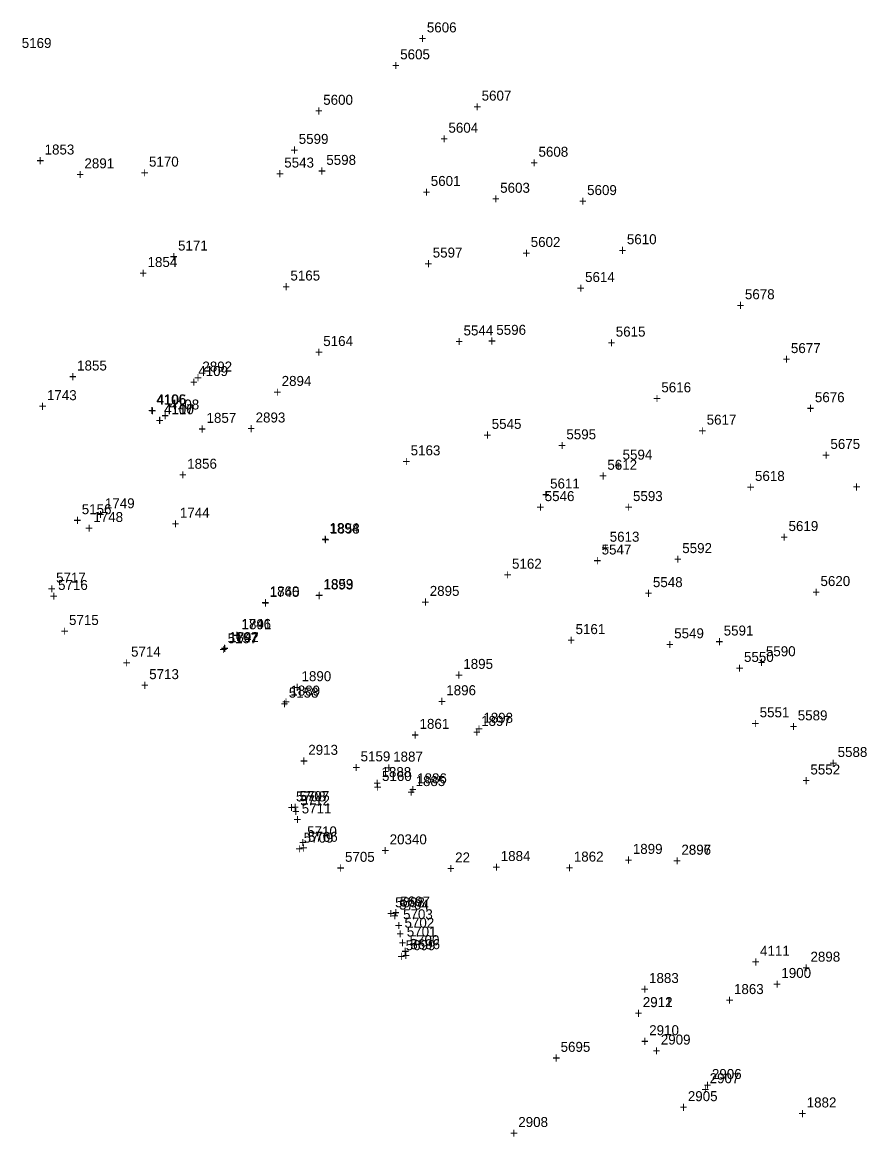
# Model space of a CAD drawing. Extents: x 1036751 to 1042192, y 772604 to 785439.
# Drawn here: x 1040253.8 to 1040463.6, y 775179.4 to 775458.3 of the extents above; entities that cross this region are included whole.
import ezdxf

# ---------------------------------------------------------------- set-up
doc = ezdxf.new("R2010")
doc.units = 0
for name, color, linetype in [('S_Control_Geodetic_ControlPoint', 7, 'Continuous'), ('S_Curb_Type_3', 7, 'Continuous'), ('S_Drainage_Culvert_Top', 7, 'Continuous'), ('S_Drainage_Invert', 7, 'Continuous'), ('S_Drainage_Waterway', 7, 'Continuous'), ('S_Fencing_ChainLink', 7, 'Continuous'), ('S_Ground_Elevation', 7, 'Continuous'), ('S_Misc_MiscItems', 7, 'Continuous'), ('S_Property_ConcPad', 7, 'Continuous'), ('S_Roadway_Centerline', 7, 'Continuous'), ('S_Roadway_Edge_Pavement', 7, 'Continuous'), ('S_Roadway_Edge_TW', 7, 'Continuous'), ('S_Traffic_Sign_SinglePost', 7, 'Continuous'), ('S_Utilities_GuyWire3', 7, 'Continuous'), ('S_Utilities_Hydrant', 7, 'Continuous'), ('S_Utilities_Pole_Power', 7, 'Continuous'), ('S_Utilities_Pole_Support3', 7, 'Continuous'), ('S_Utilities_UG_Water_Gate', 7, 'Continuous'), ('S_Utilities_UG_Water_Line', 7, 'Continuous'), ('S_Utilities_UG_Water_Shutoff', 7, 'Continuous')]:
    doc.layers.add(name, color=color, linetype=linetype)

msp = doc.modelspace()

# ---------------------------------------------------------------- texts
at = {"layer": 'S_Control_Geodetic_ControlPoint'}
for s, p in [('22', (1040362.11, 775248.06)), ('22', (1040362.11, 775248.06)), ('22', (1040362.11, 775248.06)), ('22', (1040362.11, 775248.06)), ('22', (1040362.11, 775248.06)), ('22', (1040362.11, 775248.06)), ('22', (1040362.11, 775248.06)), ('22', (1040362.11, 775248.06)), ('22', (1040362.11, 775248.06)), ('22', (1040362.11, 775248.06)), ('+', (1040360.05, 775245.31)), ('+', (1040360.05, 775245.31)), ('+', (1040360.05, 775245.31)), ('+', (1040360.05, 775245.31)), ('+', (1040360.05, 775245.31)), ('+', (1040360.05, 775245.31)), ('+', (1040360.05, 775245.31)), ('+', (1040360.05, 775245.31)), ('+', (1040360.05, 775245.31)), ('+', (1040360.05, 775245.31))]:
    msp.add_text(s, height=2.5, dxfattribs=at).set_placement(p)
at = {"layer": 'S_Curb_Type_3'}
for s, p in [('5156', (1040268.68, 775335.22)), ('+', (1040266.61, 775332.47)), ('5157', (1040305.19, 775302.92)), ('+', (1040303.13, 775300.17)), ('5158', (1040320.49, 775289.3)), ('+', (1040318.43, 775286.55)), ('5159', (1040338.45, 775273.35)), ('+', (1040336.39, 775270.6)), ('5160', (1040343.81, 775268.44)), ('+', (1040341.75, 775265.69))]:
    msp.add_text(s, height=2.5, dxfattribs=at).set_placement(p)
at = {"layer": 'S_Drainage_Culvert_Top'}
for s, p in [('2897', (1040418.73, 775250.01)), ('+', (1040416.67, 775247.26)), ('2911', (1040409.07, 775211.84)), ('+', (1040407.01, 775209.09))]:
    msp.add_text(s, height=2.5, dxfattribs=at).set_placement(p)
at = {"layer": 'S_Drainage_Invert'}
for s, p in [('2896', (1040418.71, 775249.98)), ('+', (1040416.65, 775247.23)), ('2912', (1040409.07, 775211.86)), ('+', (1040407.01, 775209.11))]:
    msp.add_text(s, height=2.5, dxfattribs=at).set_placement(p)
at = {"layer": 'S_Drainage_Waterway'}
for s, p in [('5543', (1040319.35, 775421.98)), ('+', (1040317.29, 775419.23)), ('5544', (1040364.21, 775379.96)), ('+', (1040362.15, 775377.21)), ('5545', (1040371.26, 775356.57)), ('+', (1040369.2, 775353.82)), ('5546', (1040384.53, 775338.49)), ('+', (1040382.47, 775335.74)), ('5547', (1040398.77, 775325.13)), ('+', (1040396.71, 775322.38)), ('5548', (1040411.6, 775316.96)), ('+', (1040409.54, 775314.21)), ('5549', (1040416.92, 775304.16)), ('+', (1040414.86, 775301.41)), ('5550', (1040434.39, 775298.24)), ('+', (1040432.32, 775295.49)), ('5551', (1040438.31, 775284.39)), ('+', (1040436.25, 775281.64)), ('5552', (1040451.01, 775270.07)), ('+', (1040448.95, 775267.32))]:
    msp.add_text(s, height=2.5, dxfattribs=at).set_placement(p)
at = {"layer": 'S_Fencing_ChainLink'}
for s, p in [('2907', (1040425.8, 775192.8)), ('+', (1040423.74, 775190.05)), ('2908', (1040377.91, 775181.84)), ('+', (1040375.85, 775179.09))]:
    msp.add_text(s, height=2.5, dxfattribs=at).set_placement(p)
at = {"layer": 'S_Ground_Elevation'}
for s, p in [('5606', (1040355.03, 775455.8)), ('5169', (1040253.66, 775451.9)), ('+', (1040352.97, 775453.05)), ('5605', (1040348.36, 775449.06)), ('+', (1040346.3, 775446.31)), ('5600', (1040329.1, 775437.68)), ('5607', (1040368.74, 775438.73)), ('+', (1040327.04, 775434.93)), ('+', (1040366.68, 775435.98)), ('5604', (1040360.43, 775430.69)), ('5599', (1040322.97, 775427.9)), ('+', (1040358.37, 775427.94)), ('+', (1040320.91, 775425.15)), ('5608', (1040382.97, 775424.68)), ('5170', (1040285.5, 775422.21)), ('5598', (1040329.87, 775422.65)), ('+', (1040380.91, 775421.93)), ('+', (1040283.44, 775419.46)), ('+', (1040327.81, 775419.9)), ('5601', (1040356.01, 775417.37)), ('5603', (1040373.38, 775415.66)), ('5609', (1040395.13, 775415.09)), ('+', (1040353.95, 775414.62)), ('+', (1040371.32, 775412.91)), ('+', (1040393.07, 775412.34)), ('5171', (1040292.77, 775401.21)), ('5602', (1040381.02, 775402.09)), ('5610', (1040405.08, 775402.79)), ('+', (1040290.71, 775398.46)), ('5597', (1040356.5, 775399.45)), ('+', (1040378.96, 775399.34)), ('+', (1040403.02, 775400.04)), ('+', (1040354.44, 775396.7)), ('5165', (1040320.89, 775393.7)), ('5614', (1040394.62, 775393.32)), ('+', (1040318.83, 775390.95)), ('+', (1040392.56, 775390.57)), ('5678', (1040434.62, 775389.02)), ('+', (1040432.56, 775386.27)), ('5596', (1040372.41, 775380.11)), ('5615', (1040402.3, 775379.67)), ('5164', (1040329.11, 775377.3)), ('+', (1040370.35, 775377.36)), ('+', (1040400.24, 775376.92)), ('5677', (1040446.13, 775375.54)), ('+', (1040327.05, 775374.55)), ('+', (1040444.07, 775372.79)), ('5616', (1040413.71, 775365.72)), ('+', (1040411.65, 775362.97)), ('5676', (1040452.13, 775363.25)), ('+', (1040450.07, 775360.5)), ('5617', (1040425.05, 775357.62)), ('5595', (1040389.94, 775353.96)), ('+', (1040422.99, 775354.87)), ('+', (1040387.88, 775351.21)), ('5675', (1040456.01, 775351.54)), ('5163', (1040350.98, 775349.94)), ('5594', (1040404.01, 775348.87)), ('+', (1040453.95, 775348.79)), ('+', (1040348.92, 775347.19)), ('5612', (1040400.2, 775346.33)), ('+', (1040401.94, 775346.12)), ('+', (1040398.14, 775343.58)), ('5618', (1040437.14, 775343.54)), ('5611', (1040385.87, 775341.65)), ('+', (1040435.08, 775340.79)), ('+', (1040461.6, 775340.82)), ('+', (1040383.81, 775338.9)), ('5593', (1040406.61, 775338.5)), ('+', (1040404.55, 775335.75)), ('5619', (1040445.54, 775331)), ('5613', (1040400.79, 775328.32)), ('5592', (1040418.94, 775325.48)), ('+', (1040443.48, 775328.25)), ('+', (1040398.72, 775325.57)), ('5162', (1040376.34, 775321.57)), ('+', (1040416.88, 775322.73)), ('+', (1040374.28, 775318.82)), ('5620', (1040453.53, 775317.23)), ('+', (1040451.47, 775314.48)), ('5161', (1040392.24, 775305.21)), ('5591', (1040429.31, 775304.85)), ('+', (1040390.18, 775302.46)), ('+', (1040427.25, 775302.1)), ('5590', (1040439.87, 775299.67)), ('+', (1040437.81, 775296.92)), ('5589', (1040447.84, 775283.62)), ('+', (1040445.78, 775280.87)), ('5588', (1040457.82, 775274.45)), ('+', (1040455.76, 775271.7))]:
    msp.add_text(s, height=2.5, dxfattribs=at).set_placement(p)
at = {"layer": 'S_Misc_MiscItems'}
for s, p in [('5717', (1040262.25, 775318.1)), ('+', (1040260.19, 775315.35)), ('5716', (1040262.75, 775316.25)), ('+', (1040260.69, 775313.5)), ('5715', (1040265.49, 775307.48)), ('+', (1040263.43, 775304.73)), ('5714', (1040281.01, 775299.57)), ('+', (1040278.94, 775296.82)), ('5713', (1040285.55, 775293.93)), ('+', (1040283.49, 775291.18)), ('5712', (1040323.35, 775262.33)), ('+', (1040321.29, 775259.58)), ('5711', (1040323.72, 775260.32)), ('+', (1040321.66, 775257.57)), ('5710', (1040325.07, 775254.58)), ('+', (1040323.01, 775251.83)), ('5705', (1040334.55, 775248.21)), ('+', (1040332.49, 775245.46)), ('5704', (1040348.1, 775236.26)), ('5703', (1040349.08, 775233.83)), ('+', (1040346.04, 775233.51)), ('+', (1040347.02, 775231.08)), ('5702', (1040349.44, 775231.72)), ('+', (1040347.38, 775228.97)), ('5701', (1040350.01, 775229.49)), ('+', (1040347.94, 775226.74)), ('5700', (1040350.73, 775227.35)), ('+', (1040348.66, 775224.6)), ('5695', (1040388.5, 775200.65)), ('+', (1040386.44, 775197.9))]:
    msp.add_text(s, height=2.5, dxfattribs=at).set_placement(p)
at = {"layer": 'S_Property_ConcPad'}
for s, p in [('5708', (1040322.28, 775263.33)), ('5707', (1040323.16, 775263.4)), ('+', (1040320.22, 775260.58)), ('+', (1040321.1, 775260.65)), ('5709', (1040324.21, 775253.01)), ('5706', (1040325.29, 775253.22)), ('+', (1040323.23, 775250.47)), ('+', (1040322.15, 775250.26)), ('5698', (1040347.09, 775236.82)), ('5697', (1040348.37, 775237.03)), ('+', (1040345.03, 775234.07)), ('+', (1040346.31, 775234.28)), ('5699', (1040349.73, 775226.09)), ('5696', (1040350.89, 775226.34)), ('+', (1040347.67, 775223.34)), ('+', (1040348.83, 775223.59))]:
    msp.add_text(s, height=2.5, dxfattribs=at).set_placement(p)
at = {"layer": 'S_Roadway_Centerline'}
for s, p in [('1743', (1040259.97, 775363.76)), ('+', (1040257.91, 775361.01)), ('1744', (1040293.23, 775334.34)), ('+', (1040291.17, 775331.59)), ('1860', (1040315.7, 775314.65)), ('1745', (1040315.73, 775314.53)), ('+', (1040313.64, 775311.9)), ('+', (1040313.66, 775311.78)), ('1861', (1040353.2, 775281.49)), ('+', (1040351.14, 775278.74)), ('1862', (1040391.81, 775248.27)), ('+', (1040389.75, 775245.52)), ('1863', (1040431.88, 775215.11)), ('+', (1040429.82, 775212.36))]:
    msp.add_text(s, height=2.5, dxfattribs=at).set_placement(p)
at = {"layer": 'S_Roadway_Edge_Pavement'}
for s, p in [('1853', (1040259.38, 775425.24)), ('+', (1040257.32, 775422.49)), ('1854', (1040285.14, 775397.08)), ('+', (1040283.08, 775394.33)), ('1857', (1040299.9, 775358.08)), ('+', (1040297.84, 775355.33)), ('1748', (1040271.58, 775333.26)), ('+', (1040269.52, 775330.51)), ('1894', (1040330.66, 775330.5)), ('1858', (1040330.8, 775330.37)), ('+', (1040328.6, 775327.75)), ('+', (1040328.74, 775327.62)), ('1892', (1040305.51, 775303.21)), ('1747', (1040305.54, 775303.15)), ('+', (1040303.45, 775300.46)), ('+', (1040303.48, 775300.4)), ('1895', (1040364.15, 775296.5)), ('+', (1040362.09, 775293.75)), ('1889', (1040320.88, 775289.82)), ('+', (1040318.81, 775287.07)), ('1898', (1040369.16, 775283.01)), ('+', (1040367.1, 775280.26)), ('1888', (1040343.68, 775269.42)), ('1885', (1040352.21, 775267.17)), ('+', (1040341.62, 775266.67)), ('+', (1040350.14, 775264.42)), ('1899', (1040406.57, 775250.2)), ('1884', (1040373.52, 775248.41)), ('+', (1040371.46, 775245.66)), ('+', (1040404.5, 775247.45)), ('1883', (1040410.63, 775217.88)), ('1900', (1040443.74, 775219.15)), ('+', (1040408.57, 775215.13)), ('+', (1040441.68, 775216.4)), ('1882', (1040450.08, 775186.73)), ('+', (1040448.02, 775183.98))]:
    msp.add_text(s, height=2.5, dxfattribs=at).set_placement(p)
at = {"layer": 'S_Roadway_Edge_TW'}
for s, p in [('1855', (1040267.52, 775371.18)), ('+', (1040265.46, 775368.43)), ('1856', (1040295.06, 775346.59)), ('+', (1040293, 775343.84)), ('1749', (1040274.47, 775336.7)), ('+', (1040272.41, 775333.95)), ('1893', (1040329.15, 775316.38)), ('1859', (1040329.21, 775316.49)), ('+', (1040327.08, 775313.63)), ('+', (1040327.15, 775313.74)), ('1746', (1040308.6, 775306.5)), ('1891', (1040308.67, 775306.42)), ('+', (1040306.54, 775303.75)), ('+', (1040306.61, 775303.67)), ('1890', (1040323.67, 775293.42)), ('+', (1040321.61, 775290.67)), ('1896', (1040359.89, 775289.91)), ('+', (1040357.83, 775287.16)), ('1897', (1040368.62, 775282.22)), ('+', (1040366.56, 775279.47)), ('1887', (1040346.6, 775273.3)), ('+', (1040344.54, 775270.55)), ('1886', (1040352.6, 775267.86)), ('+', (1040350.54, 775265.11))]:
    msp.add_text(s, height=2.5, dxfattribs=at).set_placement(p)
at = {"layer": 'S_Traffic_Sign_SinglePost'}
for s, p in [('2891', (1040269.35, 775421.78)), ('+', (1040267.29, 775419.03)), ('2895', (1040355.75, 775314.77)), ('+', (1040353.69, 775312.02)), ('2913', (1040325.36, 775274.99)), ('+', (1040323.3, 775272.24)), ('20340', (1040345.72, 775252.59)), ('+', (1040343.66, 775249.84)), ('2909', (1040413.57, 775202.47)), ('+', (1040411.51, 775199.72))]:
    msp.add_text(s, height=2.5, dxfattribs=at).set_placement(p)
at = {"layer": 'S_Utilities_GuyWire3'}
for s, p in [('2894', (1040318.7, 775367.32)), ('+', (1040316.64, 775364.57)), ('2905', (1040420.34, 775188.31)), ('+', (1040418.28, 775185.56))]:
    msp.add_text(s, height=2.5, dxfattribs=at).set_placement(p)
at = {"layer": 'S_Utilities_Hydrant'}
for s, p in [('2892', (1040298.86, 775370.92)), ('+', (1040296.79, 775368.17))]:
    msp.add_text(s, height=2.5, dxfattribs=at).set_placement(p)
at = {"layer": 'S_Utilities_Pole_Power'}
for s, p in [('2893', (1040312.18, 775358.17)), ('+', (1040310.11, 775355.42)), ('2898', (1040451.03, 775223.22)), ('+', (1040448.97, 775220.47))]:
    msp.add_text(s, height=2.5, dxfattribs=at).set_placement(p)
at = {"layer": 'S_Utilities_Pole_Support3'}
for s, p in [('2906', (1040426.36, 775193.86)), ('+', (1040424.3, 775191.11))]:
    msp.add_text(s, height=2.5, dxfattribs=at).set_placement(p)
at = {"layer": 'S_Utilities_UG_Water_Gate'}
for s, p in [('4106', (1040287.32, 775362.7)), ('+', (1040285.26, 775359.95)), ('4108', (1040290.63, 775361.42)), ('+', (1040288.57, 775358.67))]:
    msp.add_text(s, height=2.5, dxfattribs=at).set_placement(p)
at = {"layer": 'S_Utilities_UG_Water_Line'}
for s, p in [('4109', (1040297.83, 775369.8)), ('+', (1040295.76, 775367.05)), ('4105', (1040287.45, 775362.65)), ('+', (1040285.39, 775359.9)), ('4107', (1040289.23, 775360.2)), ('4110', (1040289.3, 775360.24)), ('+', (1040287.16, 775357.45)), ('+', (1040287.24, 775357.49)), ('4111', (1040438.41, 775224.69)), ('+', (1040436.35, 775221.94))]:
    msp.add_text(s, height=2.5, dxfattribs=at).set_placement(p)
at = {"layer": 'S_Utilities_UG_Water_Shutoff'}
for s, p in [('2910', (1040410.67, 775204.82)), ('+', (1040408.61, 775202.07))]:
    msp.add_text(s, height=2.5, dxfattribs=at).set_placement(p)

doc.saveas('drawing.dxf')
